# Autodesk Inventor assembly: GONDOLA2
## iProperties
Shininess: 64.0
Length Units: 11272
Angle Units: 11279
Time Units: 11290
Mass Units: 11286
Length Display Precision: 3
Angle Display Precision: 2
Compacted: True
Part Number: GONDOLA2
Document SubType Name: Assembly
Created: 2004-08
Designer: John Blackburn
Manufacturer: Standard
Standards Organization: Custom
Density: 0.0
Volumn: 0.0
Area: 0.0
PropertySet Name: Model Information
Control State: 0
Master: False
Checked Out: False
Author: John Blackburn
